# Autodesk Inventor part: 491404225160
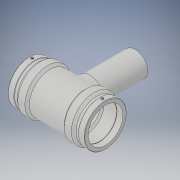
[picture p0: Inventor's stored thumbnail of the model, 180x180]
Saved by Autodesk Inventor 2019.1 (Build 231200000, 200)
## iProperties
Created: 2017-06
Part Number: 491404225160
Material: Generic
Description: PLASSON REDUCING TEE 225x160x225
Document SubType Name: Modeling
Designer: KIM
Mass: 5000.41 g
Surface Area: 5471.45 cm^2
Volume: 5000.41 cm^3
Density: 1 g/cm^3
Appearance: Default
Author: KIM
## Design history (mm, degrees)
derived "491404.ipt"
feature "Solid1::491404.ipt"
tag "TaggingFeature1"
body "Solid1"
other parameters: "d0" = 494, "d1" = 225, "d2" = 293, "d3" = 122, "d4" = 98.8, "d5" = 263.7, "d6" = 213.75, "d7" = 225, "d8" = 168 deg, "d10" = 48.8, "d11" = 16.26667, "d13" = 494, "d14" = 17.6296, "d17" = 202.5, "d18" = 225, "d19" = 3.52592, "d20" = 168 deg, "d22" = 272.49, "d23" = 293, "d25" = 135 deg, "d26" = 345.8, "d30" = 15, "d31" = 197.6, "d34" = 5 deg, "d35" = 15, "d39" = 5 deg, "d41" = 4, "d42" = 14, "d43" = 0, "d45" = 4, "d46" = 6, "d47" = 0, "d51" = 0, "d52" = 128, "d54" = 0, "d55" = 263.7, "d56" = 293, "d57" = 172.9, "d58" = 135 deg, "d59" = 122, "d60" = 122, "d61" = 135 deg, "d72" = 224.77, "d73" = 112.385, "d75" = 168, "d77" = 0, "d78" = 128, "d80" = 0, "d82" = 293.5, "d83" = 0, "d84" = 3, "d85" = 0, "d86" = 40.66667, "d87" = 267.0402, "d88" = 16.26667, "d89" = 3, "d90" = 0, "d_" = 225, "L_" = 494, "L_1" = 122, "D_" = 293, "d_2" = 12
